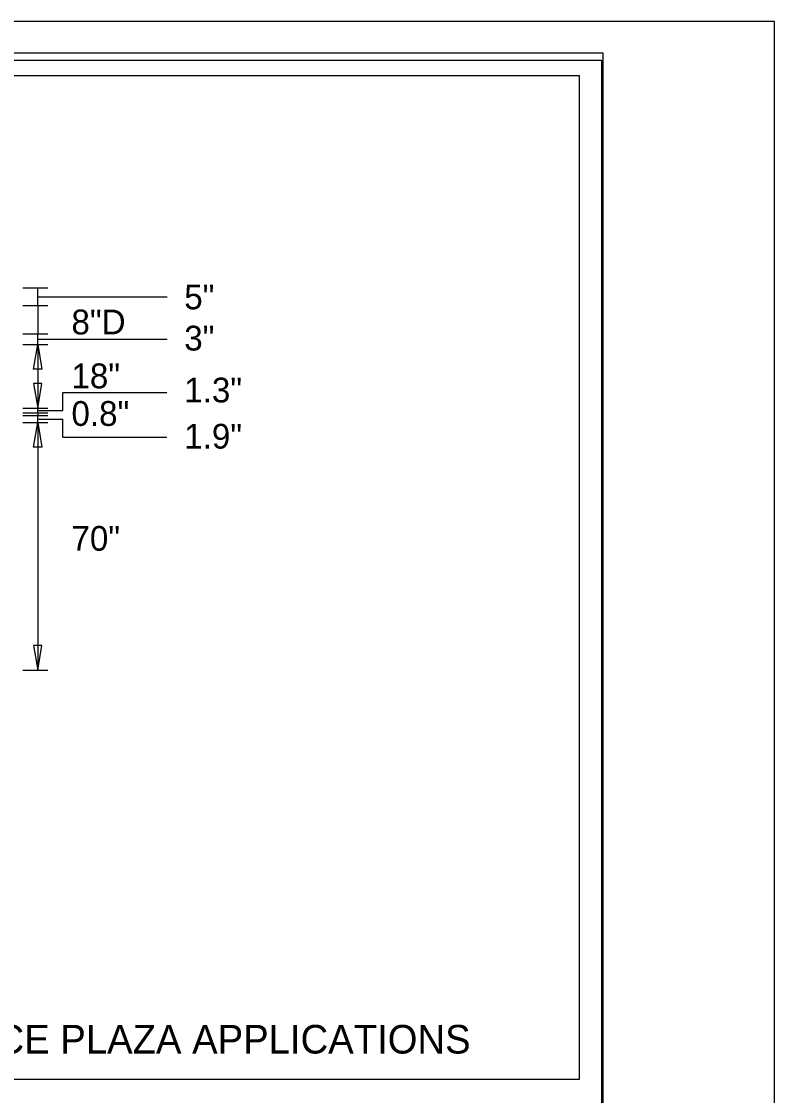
# Model space of a CAD drawing. Extents: x 17890459 to 17890580, y 17897938 to 17898017.
# Drawn here: x 17890562.32 to 17890580.04, y 17897992.09 to 17898017.37 of the extents above; entities that cross this region are included whole.
import ezdxf

# ---------------------------------------------------------------- set-up
doc = ezdxf.new("R2010")
doc.units = 0
for name, color, linetype in [('GSDims', 7, 'Continuous'), ('PlotBorder_dp', 7, 'Continuous'), ('SheetBorder_dp', 7, 'Continuous'), ('SheetLinesMisc2_dp', 7, 'Continuous')]:
    doc.layers.add(name, color=color, linetype=linetype)

msp = doc.modelspace()

# ---------------------------------------------------------------- linework, layer by layer
at = {"layer": 'GSDims'}
for p, q in [((17890562.353, 17898011.097), (17890562.937, 17898011.097)), ((17890562.703, 17898010.681), (17890562.703, 17898011.097)), ((17890562.353, 17898010.681), (17890562.937, 17898010.681)), ((17890562.353, 17898010.681), (17890562.937, 17898010.681)), ((17890562.703, 17898010.889), (17890565.749, 17898010.889)), ((17890562.703, 17898010.681), (17890562.703, 17898010.014)), ((17890562.353, 17898010.014), (17890562.937, 17898010.014)), ((17890562.353, 17898010.014), (17890562.937, 17898010.014)), ((17890562.703, 17898009.764), (17890562.703, 17898010.014)), ((17890562.353, 17898009.764), (17890562.937, 17898009.764)), ((17890562.353, 17898009.764), (17890562.937, 17898009.764)), ((17890562.703, 17898009.889), (17890565.749, 17898009.889)), ((17890562.703, 17898009.764), (17890562.703, 17898008.264)), ((17890563.291, 17898008.209), (17890563.291, 17898008.636)), ((17890563.291, 17898008.636), (17890565.742, 17898008.636)), ((17890562.353, 17898008.264), (17890562.937, 17898008.264)), ((17890562.353, 17898008.264), (17890562.937, 17898008.264)), ((17890562.353, 17898008.153), (17890562.937, 17898008.153)), ((17890562.353, 17898008.153), (17890562.937, 17898008.153)), ((17890562.703, 17898008.153), (17890562.703, 17898008.264)), ((17890562.703, 17898008.209), (17890563.291, 17898008.209)), ((17890562.703, 17898008.153), (17890562.703, 17898008.091)), ((17890562.353, 17898008.091), (17890562.937, 17898008.091)), ((17890562.353, 17898008.091), (17890562.937, 17898008.091)), ((17890562.353, 17898007.928), (17890562.937, 17898007.928)), ((17890562.353, 17898007.928), (17890562.937, 17898007.928)), ((17890562.703, 17898007.928), (17890562.703, 17898008.091)), ((17890562.703, 17898008.01), (17890563.291, 17898008.01)), ((17890562.703, 17898007.928), (17890562.703, 17898002.097)), ((17890563.291, 17898007.582), (17890563.291, 17898008.01)), ((17890563.291, 17898007.582), (17890565.742, 17898007.582)), ((17890562.353, 17898002.097), (17890562.937, 17898002.097))]:
    msp.add_line(p, q, dxfattribs=at)
for points in [[(17890562.703, 17898009.764), (17890562.801, 17898009.181), (17890562.606, 17898009.181)], [(17890562.703, 17898008.264), (17890562.801, 17898008.848), (17890562.606, 17898008.848)], [(17890562.703, 17898007.928), (17890562.801, 17898007.345), (17890562.606, 17898007.345)], [(17890562.703, 17898002.097), (17890562.801, 17898002.681), (17890562.606, 17898002.681)]]:
    msp.add_lwpolyline(points, close=True, dxfattribs=at)
at = {"layer": 'PlotBorder_dp'}
msp.add_lwpolyline([(17890458.908, 17897939.544), (17890580.045, 17897939.544), (17890580.045, 17898017.365), (17890458.908, 17898017.365)], close=True, dxfattribs=at)
at = {"layer": 'SheetBorder_dp'}
for p, q in [((17890462.946, 17898016.631), (17890576.007, 17898016.631)), ((17890576.007, 17898016.631), (17890576.007, 17897940.278))]:
    msp.add_line(p, q, dxfattribs=at)
at = {"layer": 'SheetLinesMisc2_dp'}
for p, q in [((17890463.151, 17898016.456), (17890575.98, 17898016.456)), ((17890463.151, 17898016.456), (17890575.98, 17898016.456)), ((17890575.98, 17897946.221), (17890575.98, 17898016.456)), ((17890537.078, 17898016.097), (17890575.452, 17898016.097)), ((17890575.452, 17897992.48), (17890575.452, 17898016.097)), ((17890537.078, 17897992.48), (17890575.452, 17897992.48))]:
    msp.add_line(p, q, dxfattribs=at)

# ---------------------------------------------------------------- texts
at = {"layer": 'GSDims'}
for s, height, p in [('5"', 0.5833, (17890566.151, 17898010.592)), ('8"D', 0.5833, (17890563.496, 17898010.002)), ('3"', 0.5833, (17890566.151, 17898009.622)), ('18"', 0.5833, (17890563.496, 17898008.734)), ('1.3"', 0.5833, (17890566.151, 17898008.401)), ('0.8"', 0.5833, (17890563.496, 17898007.849)), ('1.9"', 0.5833, (17890566.151, 17898007.314)), ('70"', 0.5833, (17890563.496, 17898004.911)), ('SERVICE PLAZA APPLICATIONS', 0.67331, (17890559.031, 17897993.08))]:
    msp.add_text(s, height=height, dxfattribs=at).set_placement(p)

doc.saveas('drawing.dxf')
